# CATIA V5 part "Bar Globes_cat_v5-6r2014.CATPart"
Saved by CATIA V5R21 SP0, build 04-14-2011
Part number: Bar Globes
Bounding box of the stored display mesh (mm): x -5.943 to 5.967, y -4.926 to 5, z -5.848 to 5.999
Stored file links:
  D:\CATIA V5R21 E-RESOURCES\CATIA-V5R21\catia-v5r21-prt\c16-catia-v5r20-prt\c16-catia-v5r21-tut01\CAT_V5R21_Bar Globes.CATPart
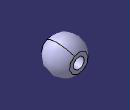
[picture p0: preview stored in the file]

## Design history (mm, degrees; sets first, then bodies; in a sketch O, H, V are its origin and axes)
Body1 (main body)
  Sketch1 on yz-plane, origin (0, 0, 0), H (0, 1, 0), V (0, 0, 1)
    arc A1 centre (0, 0) radius 6 from (6, 0) to (-6, 0) ccw
    line L1 (-6, 0) -> (6, 0)
    radius A1 = 6
    horizontal: L1 H
    coincidence: H L1
  Shaft1: profile Sketch1, axis edge of Sketch1, angle 360
  Sketch2 on yz-plane, origin (0, 0, 0), H (0, 1, 0), V (0, 0, 1)
    line L1 (-5, 7.2498) -> (5, 7.2498)
    line L2 (5, 7.2498) -> (5, -8.5554)
    line L3 (5, -8.5554) -> (1.27, -8.5554)
    line L4 (-5, -8.5554) -> (-5, 7.2498)
    line L5 (1.27, -8.5554) -> (1.27, -9.941)
    line L6 (1.27, -9.941) -> (8.2768, -9.941)
    line L7 (8.2768, -9.941) -> (8.2768, 9.8096)
    line L8 (8.2768, 9.8096) -> (-8.9775, 9.8096)
    line L9 (-8.9775, 9.8096) -> (-8.9775, -10.3789)
    line L10 (-8.9775, -10.3789) -> (-2.0145, -10.3789)
    line L11 (-2.0145, -10.3789) -> (-2.0145, -8.5554)
    point P12 (-2.0145, -8.5554)
    line L12 (-2.0145, -8.5554) -> (-5, -8.5554)
    length L1 = 10
    distance V L4 = 5
    horizontal: L1 H, L3 H, L6 H, L8 H, L10 H, L12 H
    vertical: L2 V, L4 V, L5 V, L7 V, L9 V, L11 V
    coincidence: P12 L3, L3 L12
  Pocket1: profile Sketch2, direction (-1, 0, 0), length 20, mirrored extent
  Sketch3 on face of Pocket1, origin (0.8583, -5, 1.5686), H (1, 0, 0), V (0, 0, 1)
    point P1 (-0.8583, -1.5686)
    reference intersected line E1 through (0, -1.5686) direction (-1, 0) from xy-plane
    reference intersected line E2 through (-0.8583, 0) direction (0, 1) from yz-plane
    coincidence: P1 E1, E2 P1
  Hole1: placed by Sketch3, at (0, -5, 0) direction (0, 1, 0), diameter 4, depth 10, countersink depth 1.5, countersink angle 90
